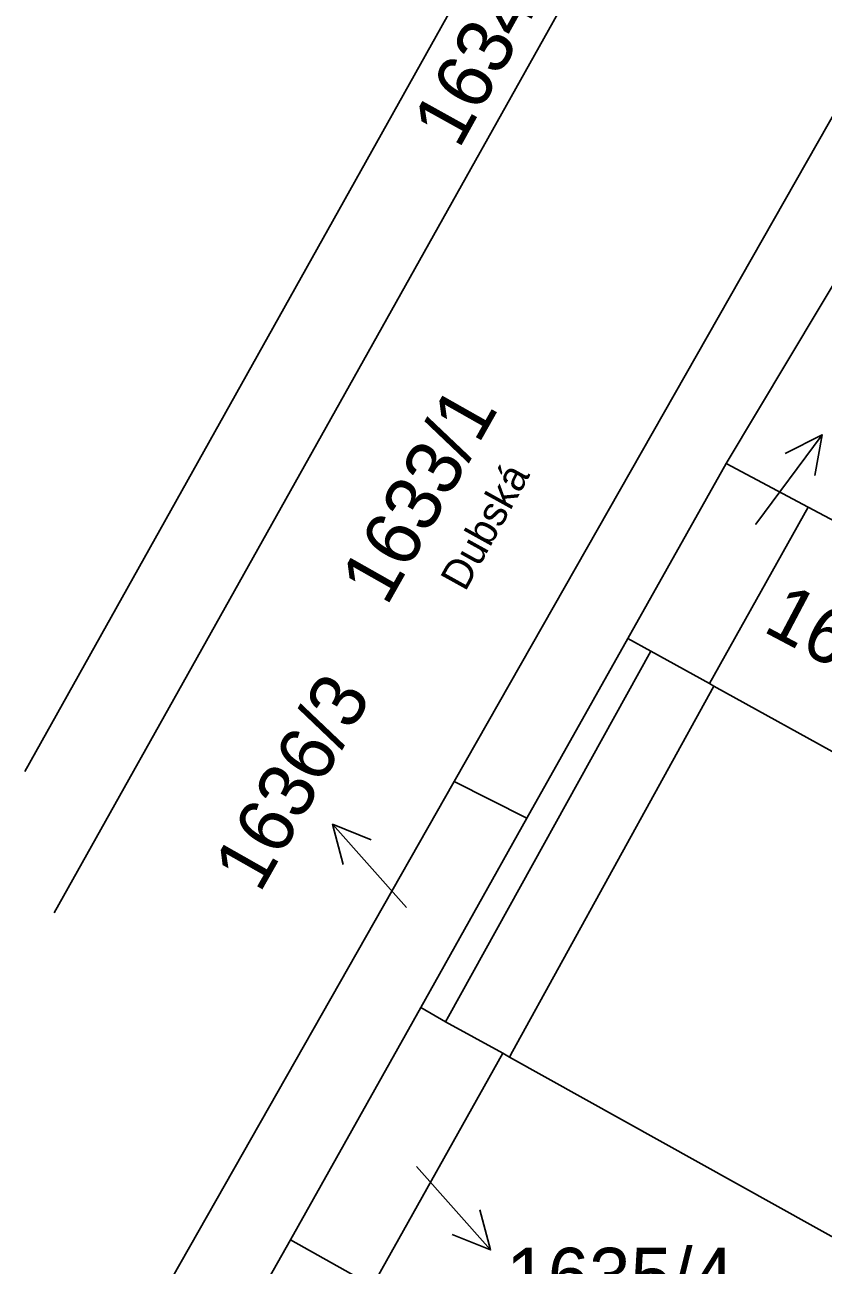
# Model space of a CAD drawing. Extents: x -762592 to -762444, y -1032635 to -1032425.
# Drawn here: x -762554.98 to -762533.47, y -1032598.54 to -1032565.13 of the extents above; entities that cross this region are included whole.
import ezdxf

# ---------------------------------------------------------------- set-up
doc = ezdxf.new("R2010")
doc.units = 0
for name, color, linetype in [('Katastr - hranice parcel', 7, 'Continuous'), ('Katastr - parcelní čísla - nedotčené ostatní', 7, 'Continuous'), ('Katastr - vnitřní kresba', 7, 'Continuous'), ('Level 16', 7, 'Continuous'), ('Popisky - ostatní', 7, 'Continuous')]:
    doc.layers.add(name, color=color, linetype=linetype)

msp = doc.modelspace()

# ---------------------------------------------------------------- linework, layer by layer
at = {"layer": 'Katastr - hranice parcel'}
for p, q in [((-762529.44, -1032539.6), (-762554.975, -1032585.241)), ((-762554.188, -1032589.048), (-762527.19, -1032540.86)), ((-762543.41, -1032585.51), (-762521.44, -1032546.89)), ((-762536.08, -1032576.94), (-762519.3, -1032548.89)), ((-762538.73, -1032581.66), (-762536.08, -1032576.94)), ((-762536.08, -1032576.94), (-762533.87, -1032578.12)), ((-762536.53, -1032582.87), (-762533.87, -1032578.12)), ((-762533.87, -1032578.12), (-762524.47, -1032583.13)), ((-762541.45, -1032586.5), (-762538.73, -1032581.66)), ((-762538.73, -1032581.66), (-762538.11, -1032582)), ((-762538.11, -1032582), (-762536.53, -1032582.87)), ((-762536.53, -1032582.87), (-762536.41, -1032582.94)), ((-762536.41, -1032582.94), (-762522.19, -1032590.8)), ((-762552.926, -1032602.238), (-762543.41, -1032585.51)), ((-762543.41, -1032585.51), (-762541.45, -1032586.5)), ((-762544.31, -1032591.6), (-762541.45, -1032586.5)), ((-762547.82, -1032597.85), (-762544.31, -1032591.6)), ((-762544.31, -1032591.6), (-762543.64, -1032591.98)), ((-762543.64, -1032591.98), (-762542.1, -1032592.83)), ((-762545.61, -1032599.09), (-762542.1, -1032592.83)), ((-762552.83, -1032606.768), (-762547.82, -1032597.85)), ((-762547.82, -1032597.85), (-762545.61, -1032599.09))]:
    msp.add_line(p, q, dxfattribs=at)
at = {"layer": 'Katastr - parcelní čísla - nedotčené ostatní'}
for p, q in [((-762533.495, -1032576.169), (-762535.28, -1032578.58)), ((-762546.685, -1032586.662), (-762544.692, -1032588.905)), ((-762542.427, -1032598.125), (-762544.42, -1032595.882))]:
    msp.add_line(p, q, dxfattribs=at)
for points in [[(-762534.492, -1032576.675), (-762533.495, -1032576.169), (-762533.688, -1032577.27)], [(-762546.395, -1032587.742), (-762546.685, -1032586.662), (-762545.648, -1032587.078)], [(-762542.718, -1032597.045), (-762542.427, -1032598.125), (-762543.465, -1032597.708)]]:
    msp.add_lwpolyline(points, dxfattribs=at)
at = {"layer": 'Katastr - vnitřní kresba'}
for p, q in [((-762543.56, -1032591.84), (-762538.11, -1032582)), ((-762541.84, -1032592.78), (-762536.41, -1032582.94)), ((-762543.64, -1032591.98), (-762543.56, -1032591.84)), ((-762542.1, -1032592.83), (-762541.92, -1032592.93)), ((-762541.92, -1032592.93), (-762541.84, -1032592.78)), ((-762541.92, -1032592.93), (-762532.13, -1032598.38))]:
    msp.add_line(p, q, dxfattribs=at)
at = {"layer": 'Level 16'}
msp.add_line((-762535.29, -1032578.59), (-762535.28, -1032578.58), dxfattribs=at)

# ---------------------------------------------------------------- texts
at = {"layer": 'Katastr - parcelní čísla - nedotčené ostatní'}
for s, rotation, p in [('1634/19', 61, (-762543.284, -1032568.503)), ('1633/1', 60.5, (-762545.229, -1032580.817)), ('1623/182', 332.1436, (-762535.13, -1032581.446)), ('1636/3', 60.447, (-762548.649, -1032588.546))]:
    msp.add_text(s, height=1.5, rotation=rotation, dxfattribs=at).set_placement(p)
msp.add_text('1635/4', height=1.5, dxfattribs=at).set_placement((-762542.003, -1032599.568))
at = {"layer": 'Popisky - ostatní'}
msp.add_text('Dubská', height=0.8, rotation=61, dxfattribs=at).set_placement((-762543.112, -1032580.417))

doc.saveas('drawing.dxf')
